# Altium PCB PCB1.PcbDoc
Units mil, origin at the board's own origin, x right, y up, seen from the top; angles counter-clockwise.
Board outline 3730 x 5970 mil, 2 copper layers (Top Layer, Bottom Layer); 100 components, 46 nets, 265 pads, 37 vias.
Unrouted connection lines stored in the file: 4.
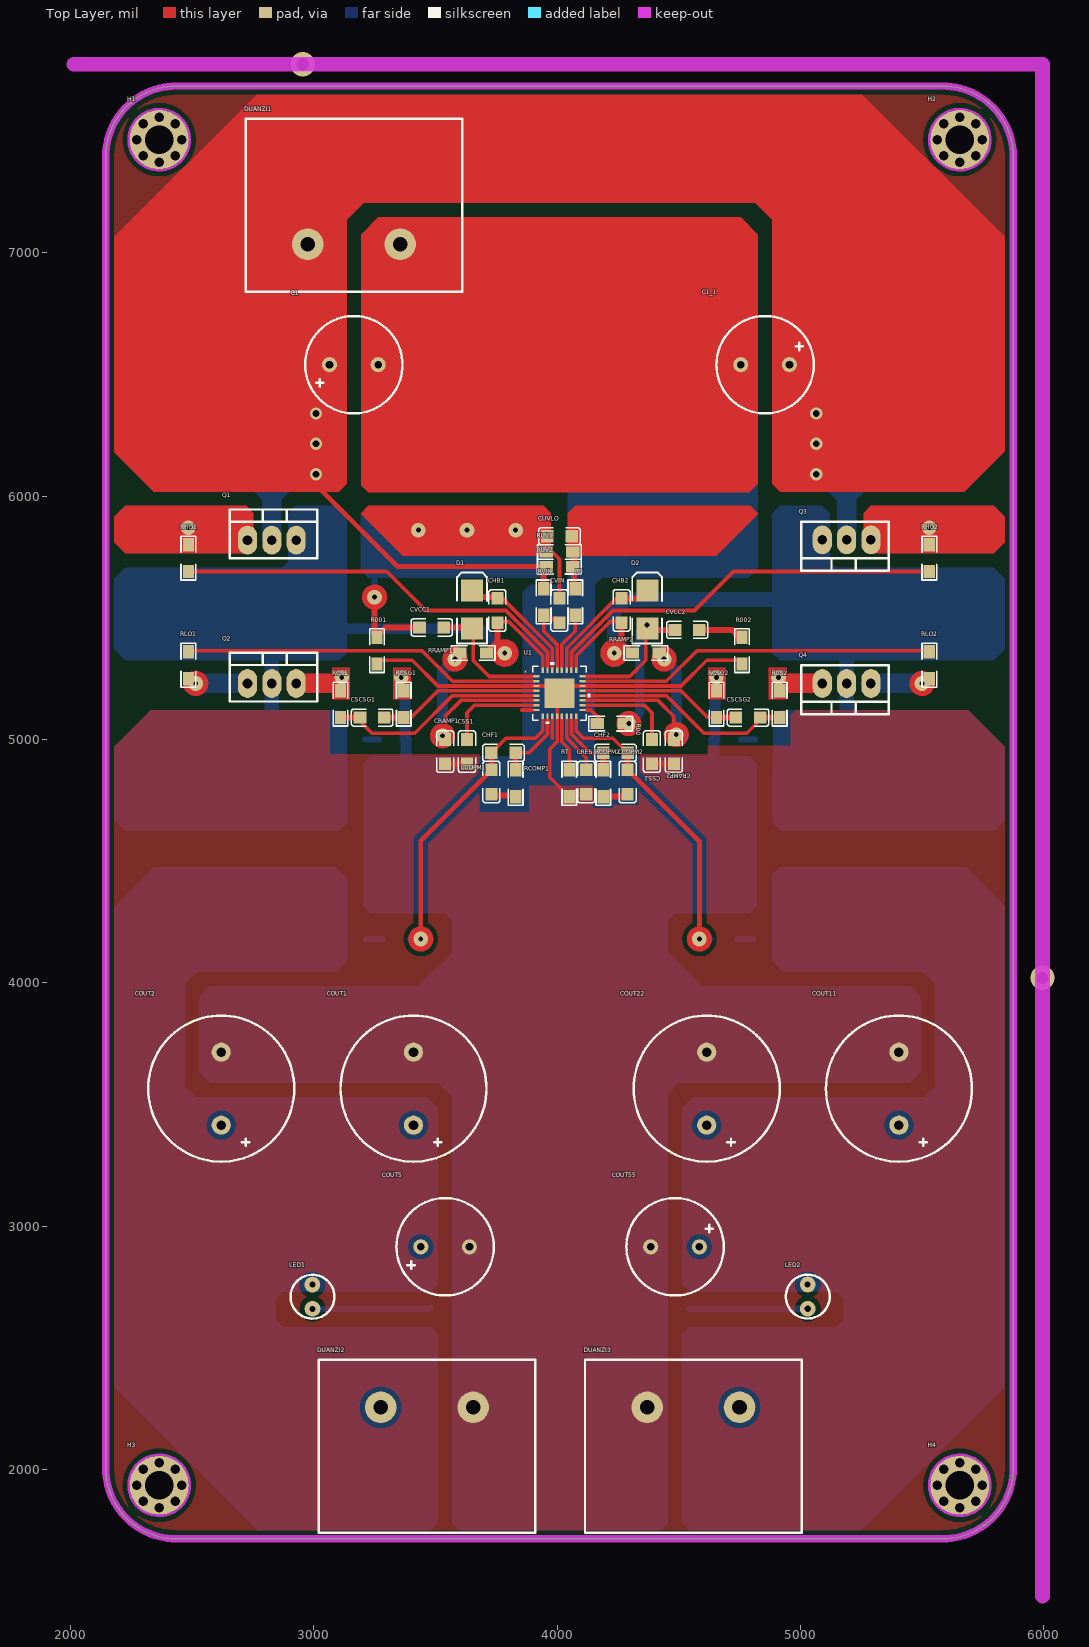
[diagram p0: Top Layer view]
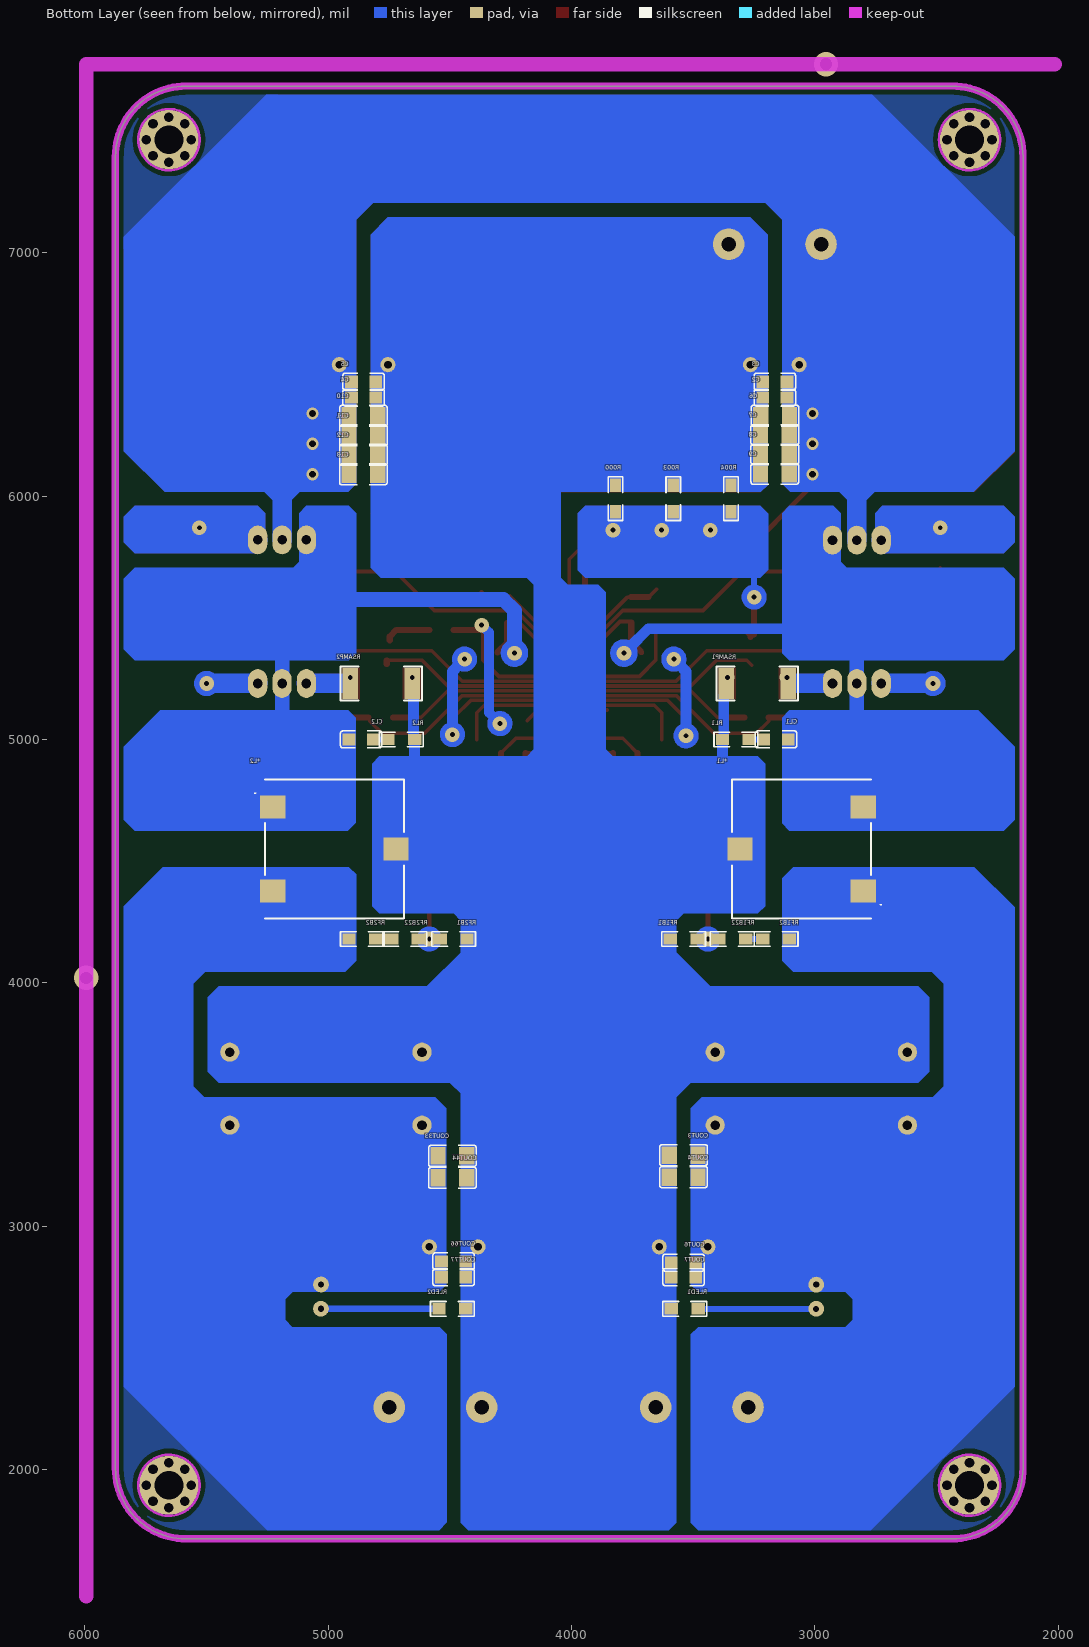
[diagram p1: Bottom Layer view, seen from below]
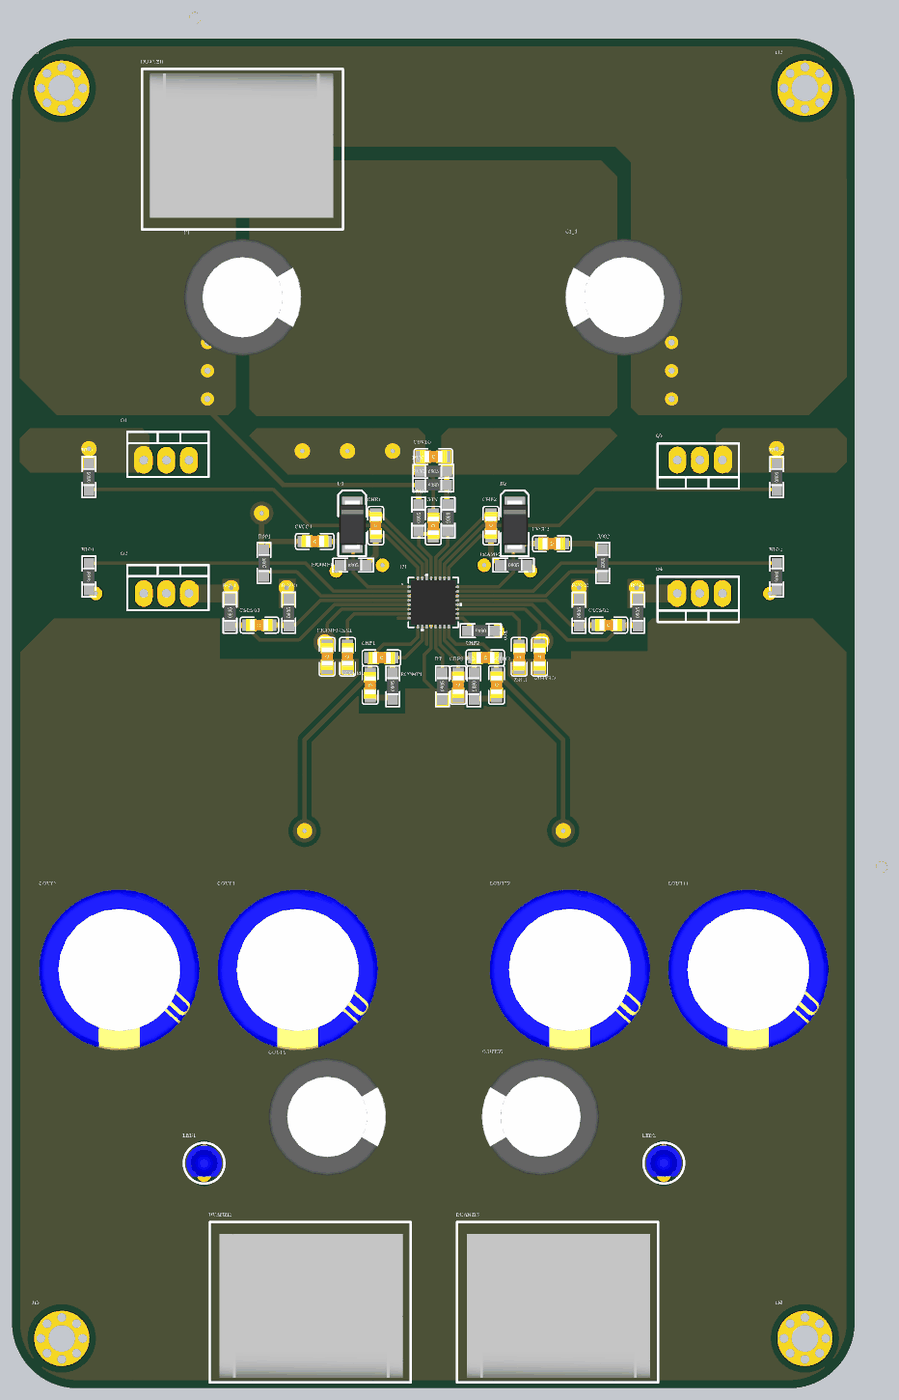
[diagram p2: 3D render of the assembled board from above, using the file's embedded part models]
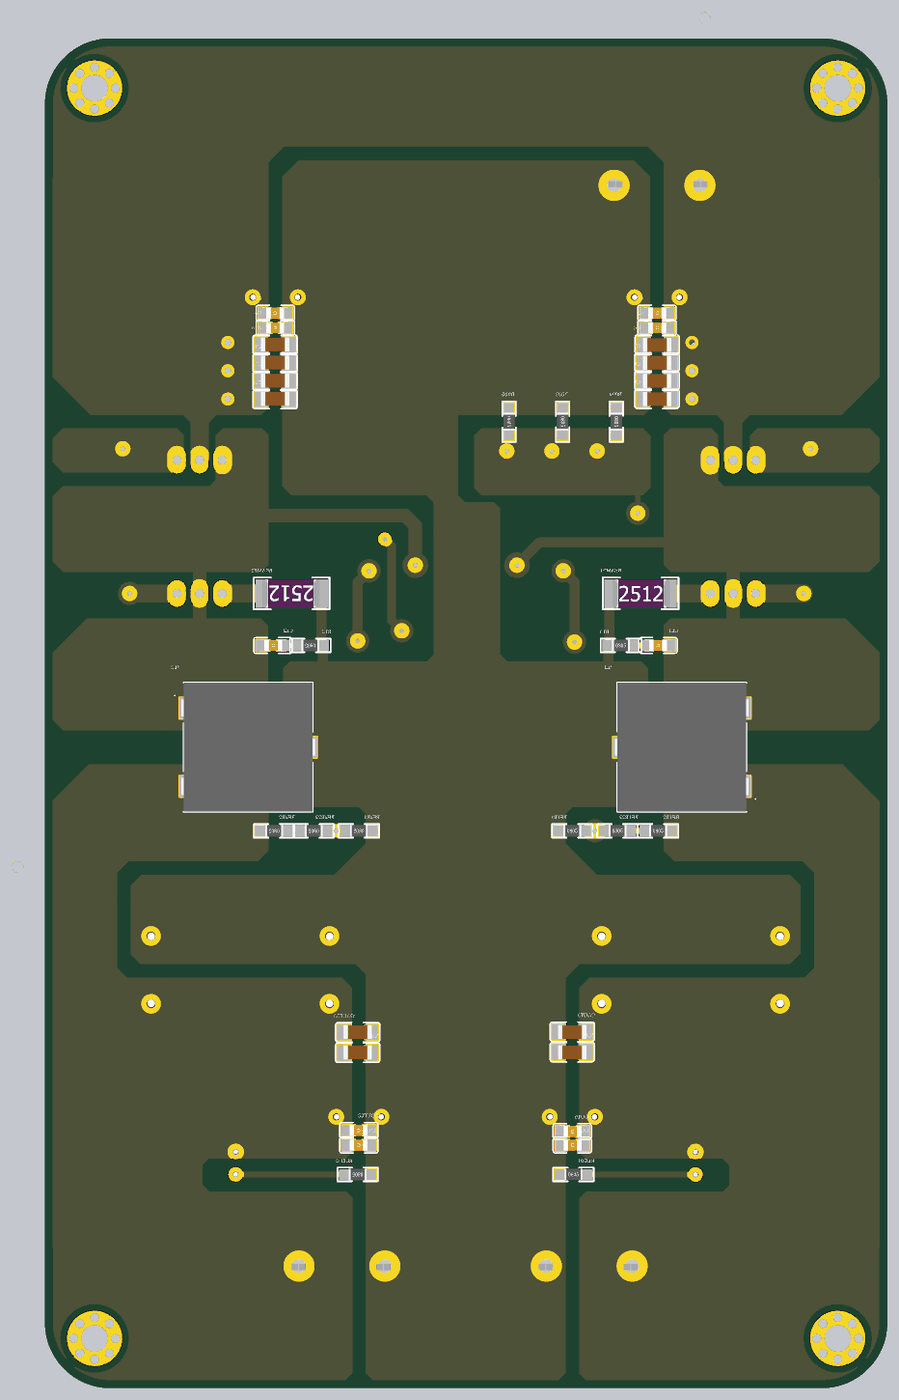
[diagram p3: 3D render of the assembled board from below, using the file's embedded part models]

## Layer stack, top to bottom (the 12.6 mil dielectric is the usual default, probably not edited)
Top Solder: solder mask 0.4, Solder Resist, Dk 3.5
Top Layer: signal copper 1.4
Dielectric 1: dielectric 12.6, FR-4, Dk 4.8
Bottom Layer: signal copper 1.4
Bottom Solder: solder mask 0.4, Solder Resist, Dk 3.5

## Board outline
2145,2005 ccw(c2435,2005) 2435,1715 5585,1715 ccw(c5585,2005) 5875,2005 5875,7395 ccw(c5585,7395) 5585,7685 2435,7685 ccw(c2435,7395) 2145,7395

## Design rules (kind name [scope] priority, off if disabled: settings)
Clearance [All] p1: gap=5 ignorepadtopadclearanceinfootprint=FALSE
PlaneConnect [All] p1: planeconnectstyle=Direct reliefexpansion=20 reliefentries=4 reliefconductorwidth=10 reliefairgap=10
PolygonConnect [All] p1: connectstyle=Direct reliefconductorwidth=10 reliefentries=4 polygonreliefangle="90 Angle" airgapwidth=10
RoutingTopology [All] p1: topology=Starburst
RoutingVias [All] p1: holewidth=28 width=50 viastyle="Through Hole" minholewidth=28 minwidth=50 maxholewidth=28 maxwidth=50
SolderMaskExpansion [All] p1: expansion=4
UnRoutedNet [All] p1: checkbadconnections=TRUE
Width [All] p1: maxlimit=100 minlimit=10 preferedwidth=25 toplayer_maxwidth=60 toplayer_prefwidth=10 minimp=50.000000 maximp=50.000000 favimp=50.000000
27 further rules are at their usual default settings.

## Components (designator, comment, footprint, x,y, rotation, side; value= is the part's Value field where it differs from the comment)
*L1 "6.1uH" CDEP147_6R1MS 3055,4550 r180 bottom
*L2 "6.1uH" CDEP147_6R1MS 4975,4550 r0 bottom
C1 "470uF" CD10 3065,6540 r180 top
C1_1 "470uF" CD10 4955,6540 r0 top
C2 "2.2uF" 0805_c 3210,6405 r180 bottom value=104
C3 "2.2uF" 0805_c 3210,6470 r180 bottom value=104
C4 "2.2uF" 0805_c 4810,6405 r0 bottom value=104
C5 "2.2uF" 0805_c 4810,6470 r0 bottom value=104
C6 "10uF" 1206 3219,6329 r180 bottom value=104
C7 "10uF" 1206 3220,6250 r180 bottom value=104
C8 "10uF" 1206 3220,6170 r180 bottom value=104
C9 "10uF" 1206 3220,6090 r180 bottom value=104
C10 "10uF" 1206 4801,6331 r0 bottom value=104
C11 "10uF" 1206 4801,6251 r0 bottom value=104
C12 "10uF" 1206 4801,6171 r0 bottom value=104
C13 "10uF" 1206 4801,6091 r0 bottom value=104
CCOPM1 "1.5nF" 0805_c 3730,4870 r270 top value=104
CCOPM2 "2.2nF" 0805_c 4290,4780 r90 top value=104
CHB1 "820nF" 0805_c 3755,5485 r90 top value=104
CHB2 "820nF" 0805_c 4265,5485 r90 top value=104
CHF1 "82pF" 0805_c 3735,4945 r0 top value=104
CHF2 "220pF" 0805_c 4195,4945 r0 top value=104
CL1 "1nF" 0805_c 3115,5000 r0 bottom value=104
CL2 "1nF" 0805_c 4910,5000 r180 bottom value=104
COUT1 "220uF" CD15 3410,3415 r270 top
COUT2 "220uF" CD15 2620,3415 r270 top
COUT3 "10uF" 1206 3595,3290 r180 bottom value=104
COUT4 "10uF" 1206 3595,3200 r180 bottom value=104
COUT5 "470uF" CD10 3440,2915 r180 top
COUT6 "2.2uF" 0805_c 3585,2850 r180 bottom value=104
COUT7 "2.2uF" 0805_c 3585,2790 r180 bottom value=104
COUT11 "220uF" CD15 5405,3415 r270 top
COUT22 "220uF" CD15 4615,3415 r270 top
COUT33 "10uF" 1206 4435,3290 r0 bottom value=104
COUT44 "10uF" 1206 4435,3200 r0 bottom value=104
COUT55 "470uF" CD10 4585,2915 r0 top
COUT66 "2.2uF" 0805_c 4440,2855 r0 bottom value=104
COUT77 "2.2uF" 0805_c 4440,2790 r0 bottom value=104
CRAMP1 "820pF" 0805_c 3540,4905 r90 top value=104
CRAMP2 "820pF" 0805_c 4480,4995 r270 top value=104
CRES "0.47uF" 0805_c 4120,4780 r90 top value=104
CSCSG1 "10nF" 0805_c 3285,5090 r180 top value=104
CSCSG2 "10nF" 0805_c 4740,5090 r0 top value=104
CSS1 "100nF" 0805_c 3630,4905 r90 top value=104
CSS2 "100nF" 0805_c 4390,4995 r270 top value=104
CUVLO "100pF" 0805_c 3965,5835 r0 top value=104
CVCC1 "1uF" 0805_c 3440,5460 r0 top value=104
CVCC2 "1uF" 0805_c 4580,5450 r180 top value=104
CVIN "0.47uF" 0805_c 4010,5575 r270 top value=104
D1 "SS54" DO-214AC 3650,5535 r90 top
D2 "SS54" DO-214AC 4370,5535 r90 top
DUANZI1 "接线端子2" HB9500 3395,7045 r0 top
DUANZI2 "接线端子2" HB9500 3235,2245 r180 top
DUANZI3 "接线端子2" HB9500 4330,2245 r180 top
H1 "Holes" "定位孔 Φ3 1" 2365,7465 r0 top
H2 "Holes" "定位孔 Φ3 1" 5655,7465 r0 top
H3 "Holes" "定位孔 Φ3 1" 2365,1935 r0 top
H4 "Holes" "定位孔 Φ3 1" 5655,1935 r0 top
LED1 "LED" LED_small 2995,2760 r270 top
LED2 "LED" LED_small 5030.39,2760.39 r270 top
Q1 "CSD18532" TO220 2830,5820 r0 top
Q2 "CSD18532" TO220 2830,5230.87 r0 top
Q3 "CSD18532" TO220 5187.91,5819.13 r180 top
Q4 "CSD18532" TO220 5187.91,5229.13 r180 top
R000 "0" 0805_r 3820,5990 r270 bottom value=1K
R00 "0" 0805_r 4220,5065 r180 top value=1K
R0 "0" 0805_r 4075,5565 r270 top value=1K
R001 "0" 0805_r 3260,5365 r270 top value=1K (schematic designator R000)
R002 "0" 0805_r 4760,5365 r270 top value=1K (schematic designator R000)
R003 "0" 0805_r 3582.5,5990 r270 bottom value=1K (schematic designator R000)
R004 "0" 0805_r 3345,5990 r270 bottom value=1K (schematic designator R000)
RCOMP1 "820K" 0805_r 3830,4820 r90 top value=1K
RCOPM2 "330K" 0805_r 4190,4820 r270 top value=1K
RCS1 "0" 0805_r 3110,5145 r90 top value=1K
RCS2 "0" 0805_r 4915,5145 r90 top value=1K
RCSG1 "0" 0805_r 3370,5145 r90 top value=1K
RCSG2 "0" 0805_r 4655,5145 r90 top value=1K
RF1B1 "2.2K" 0805_r 3540,4180 r180 bottom value=1K
RF1B2 "820" 0805_r 3160,4180 r180 bottom value=1K
RF1B22 "30K" 0805_r 3340,4180 r180 bottom value=1K
RF2B1 "2.2K" 0805_r 4485,4180 r0 bottom value=1K
RF2B2 "510" 0805_r 4860,4180 r0 bottom value=1K
RF2B22 "11K" 0805_r 4685,4180 r0 bottom value=1K
RHO1 "10" 0805_r 2485,5745 r90 top value=1K
RHO2 "10" 0805_r 5530,5745 r90 top value=1K
RL1 "10R" 0805_r 3325,5000 r180 bottom value=1K
RL2 "10R" 0805_r 4700,5000 r0 bottom value=1K
RLED1 "1K" 0805_r 3535,2660 r180 bottom
RLED2 "510" 0805_r 4490,2660 r0 bottom value=1K
RLO1 "0" 0805_r 2485,5305 r270 top value=1K
RLO2 "0" 0805_r 5530,5305 r270 top value=1K
RRAMP1 "30K" 0805_r 3655,5355 r0 top value=1K
RRAMP2 "30K" 0805_r 4365,5355 r0 top value=1K
RSAMP1 "0.01R" 2512_R 3240,5230 r180 bottom value=1K
RSAMP2 "0.01R" 2512_R 4780,5230 r0 bottom value=1K
RT "12K" 0805_r 4050,4820 r90 top value=1K
RUV1 "3.3K" 0805_r 4010,5770 r0 top value=1K
RUV2 "51K" 0805_r 4010,5710 r180 top value=1K
RVIN "0" 0805_r 3945,5565 r90 top value=1K
U1 "LM25119" WQFN 4010,5190 r0 top

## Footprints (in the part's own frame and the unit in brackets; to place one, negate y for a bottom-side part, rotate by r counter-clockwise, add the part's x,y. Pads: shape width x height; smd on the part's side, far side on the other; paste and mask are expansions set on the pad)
0805_c [mil]
  rect 52x50 smd: 1(-5,0) 2(95,0)
  silkscreen extent -40,-35 130,35, body extent -13,-28 105,28, height 37
0805_r [mil]
  rect 55.12x46 smd: 1(-55,0) 2(55,0)
  silkscreen extent -90,-30 90,30, body extent -39,-25 39,25, height 22
1206 [mil]
  rect 62.99x70.87 smd: 1(-4,1) 2(114,1)
  silkscreen extent -43,-42 153,44, body extent -8,-31 118,31, height 37
2512_R [mm]
  rect 1.65x3.2 smd: 1(-3.175,0) 2(3.305,0)
  silkscreen extent -4.19,-1.78 4.32,1.78, body extent -3.08,-1.6 3.34,1.6, height 0.58
CD10 [mil] "1000uF35V耐压"
  round 62 hole 31.5: 1(0,0) 2(-200,0)
  silkscreen extent -300,-200 100,200, body extent -360,-260 160,260, height 1000
CD15 [mm]
  round 2 hole 1: 1(0,0) 2(-7.62,0)
  silkscreen extent -11.43,-7.62 3.81,7.62, body extent -12.84,-9.03 5.22,9.02, height 35
CDEP147_6R1MS [mm]
  rect 2.65x2.4 smd: 1(6.425,-4.4) 2(6.425,4.4) 3(-6.425,0)
  silkscreen extent -7.25,-7.25 8.31,7.25, body extent -7.51,-7.25 7.51,7.25, height 8.1
DO-214AC [mm] "SMA"
  rect 2.3x2.3 smd: 1(-2.021,-0.025) 2(1.971,-0.025)
  silkscreen extent -3.57,-1.58 3.82,1.55, body extent -2.83,-1.5 2.77,1.45, height 2.9
HB9500 [mil]
  round 130 hole 60: 1(-420,-10) 2(-40,-10)
  silkscreen extent -675,-205 215,505, body extent -640,-153 171,485, height 826
LED_small [mil]
  round 65 hole 25: 1(0.39,-0.39) 2(100,0)
  silkscreen extent -40,-90 140,90, body extent -29,-79 110,79, height 205
TO220 [mm] "MOS 功率三极管封装"
  oval 2x3 hole 1: 1(-2.593,-0.022) 2(-0.053,-0.022) 3(2.487,-0.022)
  silkscreen extent -4.44,-1.91 4.7,3.17, body extent -5.21,-1.68 4.92,3.72, height 19.3
WQFN [mil]
  rect 24x10 smd paste-5: 1(-94.5,68.9) 2(-94.5,49.21) 3(-94.5,29.53) 4(-94.5,9.84) 5(-94.5,-9.84) 6(-94.5,-29.53) 7(-94.5,-49.21) 8(-94.5,-68.9) 17(94.5,-68.9) 18(94.5,-49.21) 19(94.5,-29.53) 20(94.5,-9.84) 21(94.5,9.84) 22(94.5,29.53) 23(94.5,49.21) 24(94.5,68.9)
  rect 10x24 smd paste-5: 9(-68.9,-94.5) 10(-49.21,-94.5) 11(-29.53,-94.5) 12(-9.84,-94.5) 13(9.84,-94.5) 14(29.53,-94.5) 15(49.21,-94.5) 16(68.9,-94.5) 25(68.9,94.5) 26(49.21,94.5) 27(29.53,94.5) 28(9.84,94.5) 29(-9.84,94.5) 30(-29.53,94.5) 31(-49.21,94.5) 32(-68.9,94.5)
  rect 122x122 smd paste-61: 33(0,0)
  silkscreen extent -110,-126 126,126, body extent -98,-98 98,98, height 31
"定位孔 Φ3 1" [mm]
  round 1 hole 1: 1(-2.35,0) 1(-1.662,-1.662) 1(-1.662,1.662) 1(0,-2.35) 1(0,2.35) 1(1.662,-1.662) 1(1.662,1.662) 1(2.35,0)
  round 6.2 hole 3: 1(0,0)
  Keep-Out Layer circle w0.254: c0,0 r3.2

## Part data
*L1 *L2: library part L_三端大电流电感
C1 C1_1 COUT1 COUT2 COUT5 COUT11 COUT22 COUT55: library part CAP1
C2 C3 C4 C5 C6 C7 C8 C9 C10 C11 C12 C13 CCOPM1 CCOPM2 CHB1 CHB2 CHF1 CHF2 CL1 CL2 COUT3 COUT4 COUT6 COUT7 COUT33 COUT44 COUT66 COUT77 CRAMP1 CRAMP2 CRES CSCSG1 CSCSG2 CSS1 CSS2 CUVLO CVCC1 CVCC2 CVIN: library part CAP, "Capacitor"
D1 D2: library part 1N4007, "High Conductance Fast Diode"
H1 H2 H3 H4: "holes in the corner of the bord"
LED1 LED2: library part LED1
Q1 Q2 Q3 Q4: library part "MOSFET N"
R000 R00 R0 R001 R002 R003 R004 RCOMP1 RCOPM2 RCS1 RCS2 RCSG1 RCSG2 RF1B1 RF1B2 RF1B22 RF2B1 RF2B2 RF2B22 RHO1 RHO2 RL1 RL2 RLED1 RLED2 RLO1 RLO2 RRAMP1 RRAMP2 RSAMP1 RSAMP2 RT RUV1 RUV2 RVIN: library part RES, "Resistor"

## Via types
v1: diameter 60, hole 20, Top Layer to Bottom Layer, 22 vias
v2: diameter 100, hole 50, Top Layer to Bottom Layer, 9 vias
v3: diameter 50, hole 28, Top Layer to Bottom Layer, 6 vias

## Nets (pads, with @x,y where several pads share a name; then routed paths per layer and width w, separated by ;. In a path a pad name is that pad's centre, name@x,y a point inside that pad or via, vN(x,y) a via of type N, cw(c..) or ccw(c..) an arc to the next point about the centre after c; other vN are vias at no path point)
+5: *L2.2 COUT11.1 COUT22.1 COUT33.2 COUT44.2 COUT55.1 COUT66.2 COUT77.2 DUANZI3.1 LED2.1 RF2B2.2
+12: *L1.1 COUT1.1 COUT2.1 COUT3.2 COUT4.2 COUT5.1 COUT6.2 COUT7.2 DUANZI2.2 LED1.1 RF1B2.2
FB1: CCOPM1.1 CHF1.1 RF1B1.2 RF1B22.1 U1.9 | length 1645.5
  Top Layer w15: CHF1.1 3731,4945 3751,4965 3751,4966 3790,5005 3911.1,5005 3941.1,5035 3941.1,5080
  Top Layer w20: v1(3440,4180) 3440,4211.62 3440,4584 CCOPM1.1@3730,4874
  Top Layer w25: CCOPM1.1 CHF1.1
  Top Layer w40: 3440,4211.62 cw(c3440,4180) 3450,4210 cw(c3440,4180) 3471.62,4180 cw(c3440,4180) 3440,4211.62
  Bottom Layer w25: RF1B22.1 3408.38,4180 v1(3440,4180) RF1B1.2@3465,4180
  Bottom Layer w40: RF1B22.1@3408.38,4180 cw(c3440,4180) 3471.62,4180 cw(c3440,4180) RF1B22.1@3408.38,4180
FB2: CCOPM2.2 CHF2.2 RF2B1.2 RF2B22.1 U1.16 | length 1652.5
  Top Layer w15: 4078.9,5080 4078.9,5035 4108.9,5005 4229,5005 4289,4945 CHF2.2
  Top Layer w20: CCOPM2.2@4291,4875 4585,4581 4585,4211.62 v1(4585,4180)
  Top Layer w25: CCOPM2.2@4290,4870 CCOPM2.2 CHF2.2
  Top Layer w40: 4585,4211.62 cw(c4585,4180) 4595,4210 cw(c4585,4180) 4616.62,4180 cw(c4585,4180) 4585,4211.62
  Bottom Layer w25: RF2B1.2@4560,4180 v1(4585,4180) 4616.62,4180 RF2B22.1
  Bottom Layer w40: RF2B22.1@4616.62,4180 ccw(c4585,4180) RF2B22.1@4616.62,4180
GND: *L1.3 *L2.3 C1.2 C1_1.2 C2.1 C3.1 C4.1 C5.1 C6.1 C7.1 C8.1 C9.1 C10.1 C11.1 C12.1 C13.1 COUT1.2 COUT2.2 COUT3.1 COUT4.1 COUT5.2 COUT6.1 COUT7.1 COUT11.2 COUT22.2 COUT33.1 COUT44.1 COUT55.2 COUT66.1 COUT77.1 CRAMP1.1 CRAMP2.2 CRES.1 CSS1.1 CSS2.2 CUVLO.1 CVCC1.1 CVCC2.1 CVIN.1 DUANZI1.2 DUANZI2.1 DUANZI3.2 R000.1 R000.2 R001.1 R001.2 R002.1 R002.2 R003.1 R003.2 R004.1 R004.2 RCSG1.2 RCSG2.2 RF1B1.1 RF2B1.1 RL1.1 RL2.1 RLED1.1 RLED2.1 RSAMP1.1 RSAMP2.1 RT.1 RUV1.1 U1.3 U1.12 U1.22 U1.33 | length 4238.3
  Top Layer w15: R001.1@3250,5431.5 R001.1@3260,5421.5 ; R001.2@3260,5305 3280,5325 3405,5325 3510.47,5219.53 U1.3 3980.47,5219.53 U1.33 ; RUV1.1@3975,5775 4010,5740 CVIN.1 ; RT.1 3970,4845 3970,4959.84 4000.16,4990 U1.12 4000.16,5180.16 U1.33 ; R002.2@4760,5325 4615,5325 4509.53,5219.53 U1.22 4039.53,5219.53 U1.33
  Top Layer w25: R001.1@3250,5431.5 3250,5553.38 v1(3250,5585) ; R001.1@3265.77,5421.5 3265.77,5430.77 3295,5460 CVCC1.1 ; CRAMP1.1 CSS1.1 ; RUV1.1@3960,5770 CUVLO.1@3960,5825 ; RT.1@4060,4775 CRES.1 ; CSS2.2 CRAMP2.2 ; CVCC2.1 4720,5450 4747.5,5422.5 R002.1@4747.5,5407.5 ; R002.2 R002.2@4760,5325
  Top Layer w40: 3250,5553.38 ccw(c3250,5585) 3281.62,5585 ccw(c3250,5585) 3250,5553.38
  Bottom Layer w25: v1(3250,5585) 3250,5616.62 3250,5690
  Bottom Layer w40: 3250,5616.62 cw(c3250,5585) 3281.62,5585 cw(c3250,5585) 3250,5616.62
  Bottom Layer w45: RL1.1@3375,5000 RSAMP1.1@3375,5179.49 ; 3380,4910 RL1.1 ; 4645,4910 RL2.1 ; RL2.1@4650,5000 RSAMP2.1@4650,5215
  other v1: 3360,5255 4655,5255 3430,5860 3630,5860 3830,5860
Net*L1_2: *L1.2 CHB1.1 CL1.1 Q1.3 Q2.2 RRAMP1.2 U1.32 | length 2521.8
  Top Layer w15: RRAMP1.2 RRAMP1.2@3714.56,5355 ; CHB1.1 3755,5485 3801.1,5485 3941.1,5345 3941.1,5300
  Top Layer w25: RRAMP1.2@3714.56,5360 3755,5400.44 CHB1.1
  Top Layer w50: 3816.62,5355 ccw(c3785,5355) 3816.62,5355
  Bottom Layer w45: 3110,5455 3685,5455 3762.64,5377.36 v1(3785,5355)
  Bottom Layer w50: 3762.64,5377.36 cw(c3785,5355) 3816.62,5355 cw(c3785,5355) 3762.64,5377.36
  Bottom Layer w60: 2827.91,4887.91 Q2.2 2827.91,5462.91 2927.91,5562.91 Q1.3
Net*L2_1: *L2.1 CHB2.1 CL2.1 Q3.3 Q4.2 RRAMP2.1 U1.25 | length 2464.3
  Top Layer w15: 4078.9,5300 4078.9,5345 4218.9,5485 4257.5,5485 CHB2.1@4265,5477.5
  Top Layer w25: CHB2.1@4265,5477.5 4265,5397.94 RRAMP2.1@4305.44,5357.5
  Top Layer w50: 4266.62,5355 ccw(c4235,5355) 4266.62,5355
  Bottom Layer w45: Q3.3@5087.91,5820 Q3.3
  Bottom Layer w50: 4235,5386.62 cw(c4235,5355) 4266.62,5355 cw(c4235,5355) 4235,5386.62
  Bottom Layer w60: v1(4235,5355) 4235,5386.62 4235,5530 4280,5575 4900,5575 ; Q3.3@5087.91,5820 5087.91,5572.91 5190,5470.83 Q4.2 5190,5085
NetCCOPM1_2: CCOPM1.2 RCOMP1.1 | length 97.1
  Top Layer w15: CCOPM1.2 CCOPM1.2@3735,4770
  Top Layer w25: CCOPM1.2@3735,4770 RCOMP1.1@3825,4770
NetCCOPM2_1: CCOPM2.1 RCOPM2.2 | length 104.1
  Top Layer w15: CCOPM2.1@4280,4765 CCOPM2.1
  Top Layer w25: RCOPM2.2 CCOPM2.1@4280,4765
NetCHB1_2: CHB1.2 D1.2 U1.30 | length 504.7
  Top Layer w15: D1.2@3651,5617.58 D1.2@3683.58,5585 ; CHB1.2@3755,5585 3770,5585 3980.47,5374.53 3980.47,5300
  Top Layer w25: D1.2@3683.58,5585 CHB1.2@3755,5585
NetCHB2_2: CHB2.2 D2.2 U1.27 | length 496.7
  Top Layer w15: 4039.53,5300 4039.53,5374.53 CHB2.2@4255,5590 ; D2.2@4343.42,5580 D2.2@4371,5607.58
  Top Layer w25: CHB2.2 D2.2@4343.42,5580
NetCHF1_2: CHF1.2 RCOMP1.2 U1.10 | length 291.4
  Top Layer w15: CHF1.2 3885,4945 3960.79,5020.79 3960.79,5080
  Top Layer w25: RCOMP1.2 CHF1.2
NetCHF2_1: CHF2.1 RCOPM2.1 U1.15 | length 296.4
  Top Layer w15: 4059.21,5080 4059.21,5020.79 4135,4945 CHF2.1
  Top Layer w25: RCOPM2.1@4190,4870 RCOPM2.1 CHF2.1
NetCL1_2: CL1.2 RL1.2 | length 60
  Bottom Layer w25: CL1.2 RL1.2
NetCL2_2: CL2.2 RL2.2 | length 60
  Bottom Layer w25: RL2.2 CL2.2
NetCRAMP1_2: CRAMP1.2 RRAMP1.1 U1.6 | length 1612.6
  Top Layer w15: CRAMP1.2 3540,5045 3540,5095 3605.47,5160.47 3900,5160.47
  Top Layer w40: 3540,5045 cw(c3530,5015) 3561.62,5015 cw(c3530,5015) 3540,5045 ; 3611.62,5330 ccw(c3580,5330) 3611.62,5330
  Bottom Layer w40: 3530,5046.62 cw(c3530,5015) 3561.62,5015 cw(c3530,5015) 3530,5046.62 ; 3557.64,5307.64 cw(c3580,5330) 3611.62,5330 cw(c3580,5330) 3557.64,5307.64
  Bottom Layer w45: v1(3530,5015) 3530,5046.62 3530,5280 3557.64,5307.64 v1(3580,5330)
NetCRAMP2_1: CRAMP2.1 RRAMP2.2 U1.19 | length 1607.6
  Top Layer w15: 4120,5160.47 4414.53,5160.47 4480,5095 4480,5050 CRAMP2.1
  Top Layer w40: 4471.62,5330 ccw(c4440,5330) 4471.62,5330 ; 4480,5050 cw(c4490,5020) 4521.62,5020 cw(c4490,5020) 4480,5050
  Bottom Layer w40: 4462.36,5307.64 ccw(c4440,5330) 4471.62,5330 ccw(c4440,5330) 4462.36,5307.64 ; 4490,5051.62 cw(c4490,5020) 4521.62,5020 cw(c4490,5020) 4490,5051.62
  Bottom Layer w45: v1(4440,5330) 4462.36,5307.64 4490,5280 4490,5051.62 v1(4490,5020)
NetCRES_2: CRES.2 U1.14 | length 243.3
  Top Layer w15: 4039.53,5080 4039.53,5005.47 4120,4925 CRES.2 CRES.2@4120,4870
NetCSCSG1_1: CSCSG1.1 RCSG1.1 U1.4 | length 655.5
  Top Layer w15: RCSG1.1 3371.51,5091.51 3402.14,5091.51 3510.47,5199.84 3900,5199.84
  Top Layer w25: CSCSG1.1 RCSG1.1
NetCSCSG1_2: CSCSG1.2 RCS1.1 U1.5 | length 890
  Top Layer w15: CSCSG1.2 3190,5075 3240,5025 3415,5025 3570.16,5180.16 3900,5180.16
  Top Layer w25: RCS1.1 CSCSG1.2
NetCSCSG2_1: CSCSG2.1 RCSG2.1 U1.21 | length 660.5
  Top Layer w15: 4120,5199.84 4509.53,5199.84 4617.86,5091.51 4653.49,5091.51 RCSG2.1
  Top Layer w25: RCSG2.1 CSCSG2.1
NetCSCSG2_2: CSCSG2.2 RCS2.1 U1.20 | length 874.3
  Top Layer w15: 4120,5180.16 4449.21,5180.16 4604.37,5025 4779.37,5025 CSCSG2.2@4829.37,5075
  Top Layer w25: CSCSG2.2 RCS2.1
NetCSS1_2: CSS1.2 U1.7 | length 392.8
  Top Layer w15: CSS1.2 3630,5110 3660.79,5140.79 3900,5140.79
NetCSS2_1: CSS2.1 U1.18 | length 392.8
  Top Layer w15: 4120,5140.79 4359.21,5140.79 4390,5110 CSS2.1
NetCUVLO_2: CUVLO.2 R0.1 RUV1.2 RUV2.1 | length 227.1
  Top Layer w15: CUVLO.2 CUVLO.2@4070,5835 ; R0.1@4070,5625 R0.1
  Top Layer w25: R0.1@4070,5625 CUVLO.2@4070,5835
NetCVCC1_2: CVCC1.2 D1.1 U1.1 | length 503
  Top Layer w15: D1.1@3655,5450 3655,5325 3721.1,5258.9 3900,5258.9
  Top Layer w25: CVCC1.2@3540,5460 D1.1@3645.58,5460
NetCVIN_2: CVIN.2 RVIN.1 U1.29 | length 267.8
  Top Layer w15: RVIN.1@3945,5508 3945,5445.16 4000.16,5390 4000.16,5300
  Top Layer w20: RVIN.1@3958,5495 CVIN.2@3995,5495
NetLED1_2: LED1.2 RLED1.2 | length 487.1
  Bottom Layer w25: LED1.2 3475,2660 RLED1.2@3480,2665
NetLED2_2: LED2.2 RLED2.2 | length 485.6
  Bottom Layer w25: RLED2.2 4545.39,2660.39 LED2.2
NetQ1_1: Q1.1 RHO1.2 | length 462.7
  Bottom Layer w40: 2546.62,5820 ccw(c2515,5820) 2546.62,5820
  Bottom Layer w45: Q1.1@2727.05,5820 Q1.1
  Bottom Layer w80: v1(2485,5870) 2677.05,5870 Q1.1@2727.05,5820
NetQ2_1: Q2.1 RLO1.2 | length 610.3
  Top Layer w40: 2546.62,5230 ccw(c2515,5230) 2546.62,5230
  Bottom Layer w40: 2546.62,5230 ccw(c2515,5230) 2546.62,5230
  Bottom Layer w80: v1(2515,5230) 2546.62,5230 Q2.1
NetQ2_3: Q2.3 RCS1.2 RSAMP1.2 | length 334.2
  Top Layer w80: Q2.3 3095,5230
  Bottom Layer w80: Q2.3 RSAMP1.2@3095,5230
  other v1: 3115,5255
NetQ3_1: Q3.1 RHO2.2 | length 459.4
  Bottom Layer w40: 5531.62,5820 ccw(c5500,5820) 5531.62,5820
  Bottom Layer w80: Q3.1 5340,5870 v1(5530,5870)
NetQ4_1: Q4.1 RLO2.2 | length 607.4
  Top Layer w40: RLO2.2@5531.62,5230 ccw(c5500,5230) RLO2.2@5531.62,5230
  Bottom Layer w40: 5468.38,5230 ccw(c5500,5230) 5531.62,5230 ccw(c5500,5230) 5468.38,5230
  Bottom Layer w80: Q4.1 5468.38,5230 v1(5500,5230)
NetQ4_3: Q4.3 RCS2.2 RSAMP2.2 | length 355.1
  Top Layer w15: RCS2.2 4915,5204.56 4933,5222.56 4937.56,5222.56 4945,5230
  Top Layer w80: 4945,5230 Q4.3
  Bottom Layer w80: RSAMP2.2@4925,5230 Q4.3
  other v1: 4910,5255
NetR0_2: R0.2 U1.28 | length 244.1
  Top Layer w15: 4019.84,5300 4019.84,5389.84 4075,5445 4075,5500 R0.2@4060,5515
NetR00_2: R00.2 U1.17 | length 80.6
  Top Layer w15: 4120,5121.1 4138.9,5121.1 R00.2@4182.5,5077.5
NetRF1B2_1: RF1B2.1 RF1B22.2 | length 70
  Bottom Layer w25: RF1B2.1 RF1B22.2
NetRF2B2_1: RF2B2.1 RF2B22.2 | length 65
  Bottom Layer w25: RF2B22.2 RF2B2.1
NetRHO1_1: RHO1.1 U1.31 | length 1678.2
  Top Layer w15: RHO1.1@2485,5705 2500,5690 3300,5690 3460,5530 3790,5530 3960.79,5359.21 3960.79,5300
NetRHO2_1: RHO2.1 U1.26 | length 1657
  Top Layer w15: 4059.21,5300 4059.21,5359.21 4230,5530 4565,5530 4725,5690 RHO2.1@5520,5690
NetRLO1_1: RLO1.1 U1.2 | length 1457.1
  Top Layer w15: RLO1.1@2495,5365 3445,5365 3570.79,5239.21 3900,5239.21
NetRLO2_1: RLO2.1 U1.23 | length 1457.1
  Top Layer w15: 4120,5239.21 4449.21,5239.21 4575,5365 RLO2.1@5525,5365
NetRT_2: RT.2 U1.13 | length 222.5
  Top Layer w15: 4019.84,5080 4019.84,4990.16 4050,4960 RT.2 RT.2@4050,4870
VCC: C1.1 C1_1.1 C2.2 C3.2 C4.2 C5.2 C6.2 C7.2 C8.2 C9.2 C10.2 C11.2 C12.2 C13.2 DUANZI1.1 Q1.2 Q3.2 RUV2.2 RVIN.2 | length 1736.8
  Top Layer w20: 2977.5,6077.5 3345,5710 RUV2.2
  Top Layer w25: RVIN.2 3945,5700 RUV2.2
  Bottom Layer w80: Q1.2 2827.91,6082.09 ; Q3.2 5190,6070
  other v3: 3010,6090 5065,6090 3010,6215 5065,6215 3010,6340 5065,6340
VCC2: CVCC2.2 D2.1 R00.1 U1.24 | length 1330.8
  Top Layer w15: 4120,5258.9 4298.9,5258.9 4365,5325 D2.1@4365,5444.42
  Top Layer w25: D2.1@4379.42,5450 CVCC2.2
  Top Layer w40: 4326.62,5065 ccw(c4295,5065) 4326.62,5065
  Bottom Layer w40: v1(4295,5065) 4317.36,5087.36 ; v1(4370,5470) 4340,5440 4340,5110 4317.36,5087.36 ; 4317.36,5087.36 cw(c4295,5065) 4326.62,5065 cw(c4295,5065) 4317.36,5087.36
pads on no net: H1.1 H2.1 H3.1 H4.1 U1.8 U1.11
copper on no net: | length 119.5
  Top Layer w15: 3855,5121.1 3900,5121.1 ; 3980.47,5005.47 3980.47,5080
  other v2: 5995,4020 5995,4020 5995,4020 5995,4020 5995,4020 5995,4020 5995,4020 5995,4020 2955,7775

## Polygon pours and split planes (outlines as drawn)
GND on Top Layer "Top Layer-No Net" (solid, pour order 6): 2330,5120 2140,4930 2140,1715 5870,1715 5870,4940 5690,5120
VCC on Top Layer "Top Layer-No Net" (solid, pour order 22): 5200,7685 5875,7685 5875,7010
VCC on Top Layer "Top Layer-No Net" (solid, pour order 20): 2145,7010 2145,7685 2820,7685
no net on Top Layer "Top Layer-No Net" (solid, pour order 4): 2150,5110
no net on Top Layer "Top Layer-No Net" (solid, pour order 0): 2435,7685
no net on Bottom Layer "Top Layer-No Net" (solid, pour order 88): 9555,7685
no net on Bottom Layer "Top Layer-No Net" (solid, pour order 86): 9840,5110
VCC on Bottom Layer "Top Layer-No Net" (solid, pour order 14): 5875,6975 5875,7685 5165,7685
VCC on Bottom Layer "Top Layer-No Net" (solid, pour order 12): 2855,7685 2145,7685 2145,6975
+5 on Bottom Layer "Top Layer-No Net" (solid, pour order 10): 5165.3,1715 5875.3,1715 5875.3,2425
+12 on Bottom Layer "Top Layer-No Net" (solid, pour order 8): 2165,2425 2165,1715 2875,1715

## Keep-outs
Keep-Out Layer:
  lines w30: 2145,2005 ccw(c2435,2005) 2435,1715 5585,1715 ccw(c5585,2005) 5875,2005 5875,7395 ccw(c5585,7395) 5585,7685 2435,7685 ccw(c2435,7395) 2145,7395 2145,2005
  lines w60: 2015,7775 5995,7775 ; 5995,1480 5995,7775 ; 5995,1480 5995,7775 ; 5995,1480 5995,7775 ; 5995,1480 5995,7775

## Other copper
Top Layer:
  rectangle net GND: 4620,5165 4695,5295
  rectangle net GND: 3325,5165 3400,5295
  rectangle net NetQ4_3: 4870,5165 4945,5295
  rectangle net NetQ2_3: 3075,5165 3150,5295
  pour cut-out: 3065,4940 3680,4940 3680,4700 3885,4700 3885,4810 4340,4810 4340,4940 4620,4940 4620,4975 4960,4975 4960,5100 4990,5130 5880,5130 5880,5265 3065,5265
  pour cut-out: 2145,7780
  region net NetQ3_1: 4075,5960 4045,5930 4045,5785 4075,5755 4655,5755 4827.5,5927.5 4795,5960
  region net GND: 3945,5960 3975,5930 3975,5785 3945,5755 3365,5755 3192.5,5927.5 3225,5960
  region net NetQ1_1: 2180,5915 2225,5960 2722.5,5960 2752.5,5930 2752.5,5797.5 2720,5765 2225,5765 2180,5810
  region net NetQ3_1: 5840,5810 5795,5765 5290,5765 5260,5795 5260,5930 5290,5960 5795,5960 5840,5915
  region net VCC: 2765,7650 2180,7065 2180,6180 2342.5,6017.5 3102.5,6017.5 3135,6050 3135,7650
  region net GND: 3265,7145 3195,7075 3195,6045 3225,6015 4080,6015 4080,7145
  region net GND: 4045,7145 4045,6015 4790,6015 4825,6050 4825,7075 4755,7145
  region net VCC: 3135,7135 3205,7205 4815,7205 4885,7135 4885,7650 3135,7650
  region net VCC: 4885,7650 4885,6050 4917.5,6017.5 5672.5,6017.5 5840,6185 5840,7065.02 5254.99,7650
Bottom Layer:
  region net +12: 2180,2760 2180,2340 2770,1750 3480,1750 3510,1780 3510,2555 3480,2585 2875,2585 2845,2615 2845,2700 2905,2760
  region net +5: 5840,2760 5840,2340 5250,1750 4545,1750 4512.5,1782.5 4512.5,2555 4542.5,2585 5147.5,2585 5177.5,2615 5177.5,2700 5117.5,2760
  region net GND: 4452.5,4127.5 4595,3985 5450,3985 5495,3940 5495,3635 5450,3590 4500,3590 4452.5,3542.5
  region net GND: 3572.5,4127.5 3430,3985 2575,3985 2530,3940 2530,3635 2575,3590 3510,3590 3572.5,3527.5
  region net +12: 2520,4045 2470,3995 2470,3575 2515,3530 3465,3530 3510,3485 3510,2760 3480,2730 2180,2730 2180,4310 2345,4475 2495,4475 2520,4450
  region net +5: 5505,4045 5555,3995 5555,3575 5510,3530 4560,3530 4515,3485 4515,2760 4545,2730 5840,2730 5840,4315 5680,4475 5530,4475 5505,4450
  region net GND: 4455,4255 4485,4285 3540,4285 3570,4255 3570,1780 3600,1750 4425,1750 4455,1780
  region net GND: 3235,4930 3205,4900 3205,4315 3235,4285 4790,4285 4820,4315 4820,4900 4790,4930
  region net GND: 4045,5695 4045,5665 4015,5635 4015,5600 4150,5600 4155,5595 4155,5635 4185,5665 4185,5695
  region net +5: 5640,4045 5665,4070 5665,4445 5635,4475 4915,4475 4885,4445 4885,4090 4930,4045
  region net +12: 3090,4045 3135,4090 3135,4430 3090,4475 2385,4475 2355,4445 2355,4075 2385,4045
  region net Net*L2_1: 5795,4625 5840,4670 5840,4970 5690,5120 4917.5,5120 4887.5,5090 4887.5,4657.5 4920,4625
  region net Net*L1_2: 3105,4625 3134.99,4654.99 3135,5090 3105,5120 2330,5120 2180,4970 2180,4670 2225,4625
  region net GND: 3860,4960 3827.5,4927.5 4187.5,4927.5 4155,4960 4155,5605 4125,5635 3890,5635 3860,5605
  region net GND: 4785,5665 4825,5705 4825,6045 4045,6045 4045,5695 4075,5665
  region net GND: 3225,5960 3192.5,5927.5 3192.5,5697.5 3225,5665 3945,5665 3975,5695 3975,5930 3945,5960
  region net NetQ1_1: 2752.5,5930 2722.5,5960 2225,5960 2180,5915 2180,5810 2225,5765 2720,5765 2752.5,5797.5
  region net Net*L1_2: 2925,5960 2895,5930 2895,5730 2870,5705 2225,5705 2180,5660 2180,5370 2225,5325 3105,5325 3135,5355 3135,5930 3105,5960
  region net VCC: 2755,6017.5 2797.5,5975 2857.5,5975 2900,6017.5
  region net VCC: 5117.5,6017.5 5160,5975 5220,5975 5262.5,6017.5
  region net NetQ3_1: 5260,5795 5290,5765 5795,5765 5840,5810 5840,5915 5795,5960 5290,5960 5260,5930
  region net Net*L2_1: 4915,5325 5795,5325 5840,5370 5840,5660 5795,5705 5145,5705 5120,5730 5120,5930 5090,5960 4915,5960 4885,5930 4885,5355
  region net VCC: 3135,7135 3205,7205 4815,7205 4885,7135 4885,7650 3135,7650
  region net VCC: 4885,7650 4885,6050 4917.5,6017.5 5672.5,6017.5 5840,6185 5840,7065.83 5255.8,7650
  region net GND: 4045,7145 4045,6017.5 4825,6017.5 4825,7075 4755,7145
  region net GND: 3265,7145 3195,7075 3195,6045 3222.5,6017.5 4100,6017.5 4100,7145
  region net VCC: 2764.19,7650 2180,7065.82 2180,6185 2347.5,6017.5 3102.5,6017.5 3135,6050 3135,7650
